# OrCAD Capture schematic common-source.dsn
size A
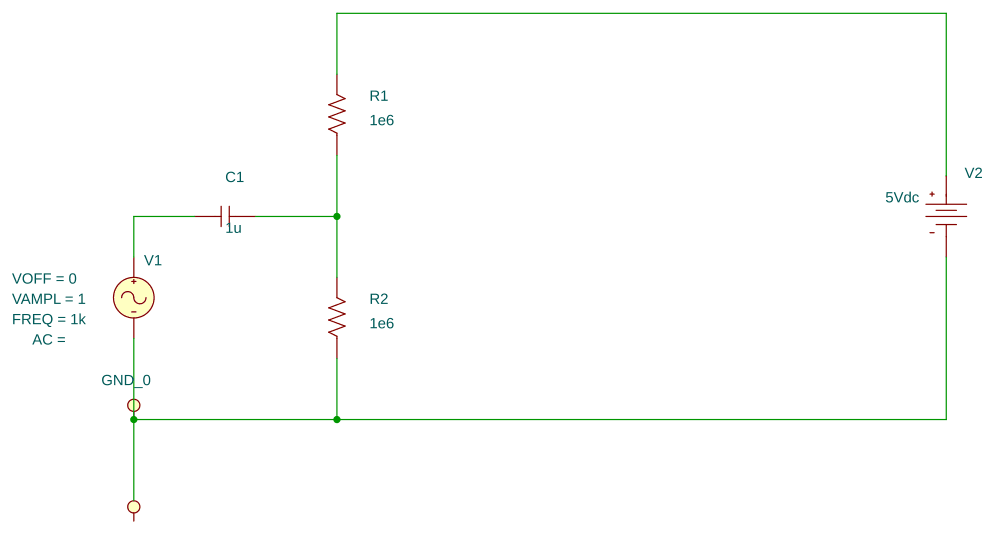
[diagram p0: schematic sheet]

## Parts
C1  1u  [cap196]
R1  1e6  [AXRC05]
R2  1e6  [AXRC05]
V1  VSIN
V2  VDC

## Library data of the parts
C1 = C
R1 R2 = R
V1 = VSIN: FREQ: 1k; VAMPL: 1; VOFF: 0
V2 = VDC: DC: 5Vdc

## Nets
0: R2.1 V1.2(-) V2.1(-)
N14403: C1.1 V1.1(+)
N14412: C1.2 R1.1 R2.2
N14481: R1.2 V2.0(+)
